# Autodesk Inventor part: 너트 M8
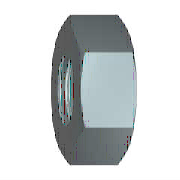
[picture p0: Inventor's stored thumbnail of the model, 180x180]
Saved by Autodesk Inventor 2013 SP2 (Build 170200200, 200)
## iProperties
IsCustomPart: 1
Created: 2012-02
Part Number: 너트 M8
Material: 강철, 연강
Description: 6각 너트 및 6각 가는 너트
Document SubType Name: Modeling
Standard: KS B 1012
Designer: mduedu
Standards Organization: KS
Language: ko-KR
Size Designation: M 8
Categories: <MemberInstance><Categories><Category DisplayName="조임쇠" InternalName="e4da775c-781d-43d5-af7c-5136215cf5a6" Mnemonic="FSTN"><Category DisplayName="너트" InternalN
Density: 1 g/cm^3
Author: mduedu
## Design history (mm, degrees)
sketch "스케치1"
  geometry: L1 (-7.506, 0)-(-3.753, 6.5); L2 (-3.753, 6.5)-(3.753, 6.5); L3 (3.753, 6.5)-(7.506, 0); L4 (7.506, 0)-(3.753, -6.5); L5 (3.753, -6.5)-(-3.753, -6.5); L6 (-3.753, -6.5)-(-7.506, 0); 2 further points
  constraints: 12 end point, 1 coincident, 1 horizontal, 11 other
  dimensions: "d0" = 15.01111 distance of L3.end L1.start (= 1.1547 x SW)
extrude "본체" new body sketch "스케치1" distance "d1" = 5 (= KOH); taper "d2" = 0 deg
sketch "스케치2"
  geometry: L1 (0, 3.753)-(0, 7.506) reference; L2 (0, 7.506)-(5, 7.506) reference; L3 (5, 3.753)-(5, 7.506) reference; L4 (-1, 0)-(6, 0) reference; L5 (0.581, 7.506)-(0, 6.5); L6 (4.419, 7.506)-(5, 6.5)
  constraints: 4 end point, 4 point on line
  dimensions: "d3" = 30 deg angle of L1 L5 (= ANG1); "d4" = 30 deg angle of L3 L6 (= ANG2); "d5" = 13 diameter of L5.end L4 (= SW0); "d6" = 13 diameter of L6.end L4 (= SW01)
revolve "모따기1" sketch "스케치2" stored, may be unused: angle "d7" = 90 deg
sketch "스케치3"
  geometry: A1 r 6.5 centre (0, 0) between (-3.25, -5.629) and (3.25, -5.629) reference; 1 further point
  constraints: 1 coincident
hole "스레드" sketch "스케치3" at (0, 0) diameter "d25" = 6.647; stored, may be unused: countersink angle "d29" = 82 deg, drill point angle "d31" = 118 deg; dims "d26" = 6, "d27" = 4, "d28" = 2, "d30" = 8
workaxis "Work Axis1"
workplane "Work Plane1"
body "Solid1"
chamfer "모따기2" distance "d8" = 0.67658 (= -0.5 x GD1 + 0.5 x NND); stored, may be unused: angle "d9" = 30 deg, second distance "d40" = 0.67658 (= -0.5 x GD1 + 0.5 x NND)
chamfer "모따기3" distance "d10" = 0.67658 (= -0.5 x GD1 + 0.5 x NND); stored, may be unused: angle "d11" = 30 deg, second distance "d41" = 0.67658 (= -0.5 x GD1 + 0.5 x NND)
other parameters: "ANG1" = 30 deg [user parameter; used in 1 equation term], "ANG2" = 30 deg [user parameter; used in 1 equation term], "NND" = 8 [user parameter; used in 4 equation terms], "KOH" = 5 [user parameter; used in 1 equation term], "SW" = 13 [user parameter; used in 4 equation terms], "SW0" = 13 (= SW) [user parameter; used in 1 equation term], "SW01" = 13 (= SW) [user parameter; used in 1 equation term], "GD1" = 6.64684 (computed from THREADDIA, PTC, TOA) [user parameter; used in 4 equation terms], "d13" = 0, "d14" = 0, "d39" = 0, "d42" = 0, "GUL" = 0.67658 (= 0.541266 x PTC) [user parameter], "TPU" = 8 (computed from PTC) [user parameter], "THREADDIA" = 8 [user parameter; used in 1 equation term], "TOA" = 30 deg [user parameter; used in 1 equation term], "PTC" = 1.25 [user parameter; used in 4 equation terms], "E0" = 15.015 (= 1.155 x SW) [user parameter], "GAL" = 0.67658 (= 0.541266 x PTC) [user parameter]
